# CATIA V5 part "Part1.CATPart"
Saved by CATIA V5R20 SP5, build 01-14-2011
Part number: Part1
Bounding box of the stored display mesh (mm): x -50.255 to 11.639, y -11.51 to 11.51, z 0 to 50.259
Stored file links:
  C:\Documents and Settings\Student\桌面\考试\Part1.CATPart
  Part3.CATPart
  Part4.CATPart
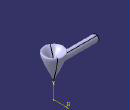
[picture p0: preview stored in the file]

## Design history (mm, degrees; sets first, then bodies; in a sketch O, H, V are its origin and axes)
Body1 (main body)
  Sketch1 on yz-plane, origin (0, 0, 0), H (0, 1, 0), V (0, 0, 1)
    axis line L1 (0, 60) -> (0, -70)
    point P1 (0, 60)
    spline S1 through (0, 20) (10, 50) (0, 40)
    line L2 (0, 40) -> (0, 20)
    point P3 (0, 40)
    point P4 (0, 20)
    point P5 (0, 20)
    point P6 (0, 40)
    coincidence: P1 V, P5 L1, P6 L1, P6 P3, P5 P4
    vertical: L1 V, L2 V
  Shaft1: profile Sketch1, axis Sketch1.L1, angle 360
  Plane1 to Plane3: stored without definition
  Sketch2 on yz-plane, origin (0, 0, 0), H (0, 1, 0), V (0, 0, 1)
    axis line L1 (0, 10) -> (0, -40)
    point P1 (0, 10)
    coincidence: P1 V
    vertical: L1 V
  DatumSurface1
  Sketch3 on zx-plane, origin (0, 0, 0), H (-1, 0, 0), V (0, 0, 1)
    line L1 (5.2555, 42.8143) -> (50.2555, 42.8143)
    line L2 (50.2555, 42.8143) -> (50.2555, 38.906)
    line L3 (50.2555, 38.906) -> (5.2555, 38.906)
    line L4 (5.2555, 38.906) -> (5.2555, 42.8143)
    length L1 = 45
    horizontal: L1 H, L3 H
    vertical: L2 V, L4 V
  Shaft2: profile Sketch3, axis Sketch3.L3, angle 360
  DatumSurface2 to DatumSurface4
